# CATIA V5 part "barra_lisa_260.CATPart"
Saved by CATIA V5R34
Part number: Part5
Bounding box of the stored display mesh (mm): x -4 to 4, y -3.991 to 3.991, z -130.1 to 130.1
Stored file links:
  C:\Users\Apolinar\Desktop\cnc\barra_lisa_260.CATPart
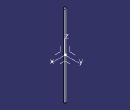
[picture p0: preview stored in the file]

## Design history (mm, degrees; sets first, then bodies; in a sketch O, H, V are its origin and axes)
AxisSystem1: origin (0, 0, 0), X (1, 0, 0), Y (0, 1, 0), Z (0, 0, 1)
Body1 (main body)
  Sketch1 on XY plane of AxisSystem1, origin (0, 0, 0), H (1, 0, 0), V (0, 1, 0)
    circle A1 centre (0, 0) radius 4
    radius A1 = 4
  Pad1: profile Sketch1, direction (0, 0, 1), length 130.1, mirrored extent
